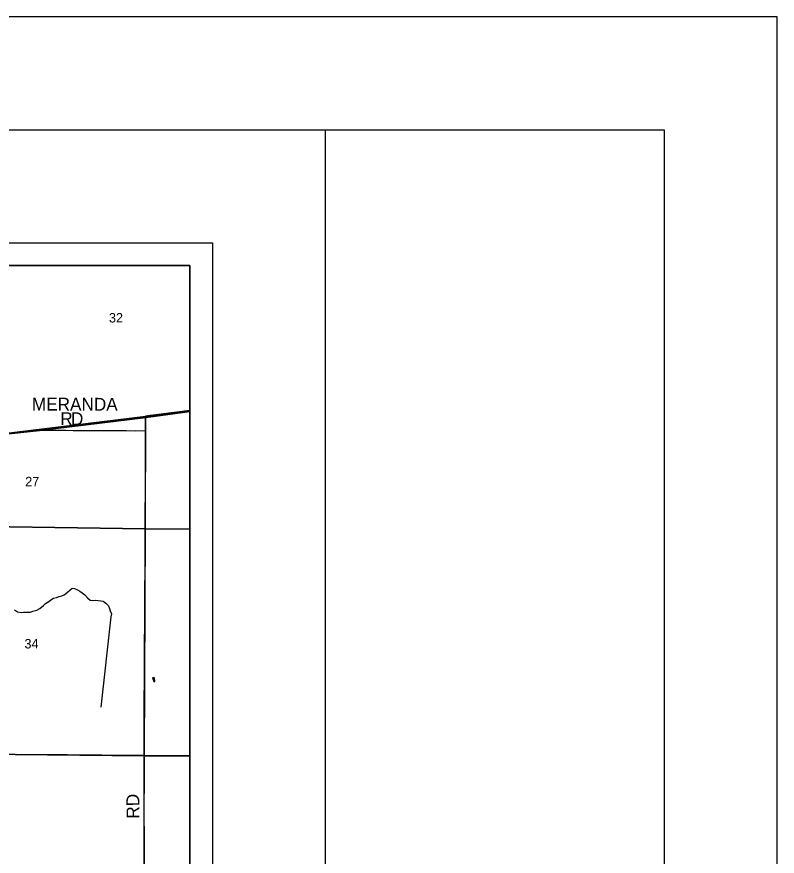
# Model space of a CAD drawing. Extents: x 0 to 1391, y -24 to 440.
# Drawn here: x 612.7 to 680, y 365.7 to 440 of the extents above; entities that cross this region are included whole.
import ezdxf

# ---------------------------------------------------------------- set-up
doc = ezdxf.new("R2010")
doc.units = 0
for name, color, linetype in [('GM_X_County_Road', 7, 'Continuous'), ('GM_X_County_Road_Text', 7, 'Continuous'), ('GM_X_Minor_Lake', 7, 'Continuous'), ('GM_X_Minor_River', 7, 'Continuous'), ('GM_X_Section', 7, 'Continuous'), ('GM_X_Section_Text', 7, 'Continuous'), ('GM_X_Township', 7, 'Continuous'), ('SH_Border', 7, 'Continuous'), ('SH_Cut_Line', 7, 'Continuous'), ('SH_Data', 7, 'Continuous')]:
    doc.layers.add(name, color=color, linetype=linetype)

msp = doc.modelspace()

# ---------------------------------------------------------------- linework, layer by layer
at = {"layer": 'GM_X_County_Road'}
for points in [[(624.066, 403.373), (624.064, 403.734), (624.056, 404.256), (624.058, 404.378), (624.061, 404.422), (624.064, 404.452), (624.069, 404.484), (624.077, 404.512), (624.085, 404.538), (624.099, 404.565), (624.107, 404.579), (624.116, 404.593), (624.129, 404.61), (624.147, 404.628), (624.171, 404.649), (624.196, 404.667), (624.224, 404.682), (624.255, 404.694), (624.289, 404.704), (624.327, 404.712), (624.366, 404.718), (624.473, 404.736), (625.011, 404.799), (625.098, 404.808), (625.531, 404.859), (626.147, 404.935), (626.627, 404.996), (627.219, 405.072), (627.785, 405.147), (628, 405.176)], [(604.058, 402.49), (604.456, 402.485), (604.969, 402.485), (605.655, 402.495), (606.005, 402.507), (606.316, 402.525), (606.787, 402.571), (607.536, 402.653), (608.265, 402.737), (608.882, 402.808), (609.301, 402.856), (610.005, 402.937), (610.372, 402.978), (610.819, 403.03), (611.574, 403.115), (612.094, 403.175), (613.214, 403.313), (613.856, 403.385), (614.215, 403.415), (614.474, 403.427), (614.788, 403.431), (615.226, 403.426)], [(615.226, 403.426), (616.325, 403.416), (617.005, 403.408), (617.667, 403.401), (618.164, 403.395), (618.985, 403.388), (619.42, 403.387), (620.385, 403.386), (620.873, 403.384), (621.363, 403.378), (621.731, 403.377), (622.377, 403.374), (623.197, 403.369), (624.066, 403.373)], [(624.033, 394.685), (624.034, 395.355), (624.047, 396.709), (624.05, 397.356), (624.05, 398.462), (624.052, 398.996), (624.056, 399.53), (624.059, 400.313), (624.063, 401.121), (624.065, 401.804), (624.067, 402.388), (624.066, 403.373)], [(623.942, 374.658), (623.944, 375.622), (623.942, 376.604), (623.938, 377.312), (623.948, 378.43), (623.958, 379.772), (623.964, 381.04), (623.974, 382.829), (623.978, 383.96), (623.979, 384.519), (623.989, 386.271), (623.997, 387.837), (624.005, 388.583), (624.012, 389.403), (624.02, 390.857), (624.022, 391.453), (624.027, 392.236), (624.03, 393.23), (624.029, 393.64), (624.033, 394.436), (624.033, 394.685)], [(624.033, 394.685), (624.095, 394.685), (624.369, 394.687), (625.189, 394.686), (627.091, 394.683), (628, 394.684)], [(612.641, 374.74), (613.834, 374.729), (614.977, 374.718), (615.648, 374.713), (616.294, 374.708), (617.151, 374.702), (617.971, 374.695), (618.705, 374.691), (620.208, 374.678), (621.488, 374.669), (622.246, 374.662), (622.83, 374.657), (623.427, 374.653), (623.775, 374.657), (623.942, 374.658)], [(623.916, 359.361), (623.916, 359.68), (623.919, 360.426), (623.916, 360.96), (623.914, 361.42), (623.915, 361.904), (623.922, 362.761), (623.924, 363.433), (623.933, 364.588), (623.963, 365.333), (623.974, 365.855), (623.977, 366.29), (623.969, 367.47), (623.962, 368.129), (623.958, 368.663), (623.955, 369.222), (623.947, 370.204), (623.947, 370.937), (623.942, 372.764), (623.942, 373.46), (623.941, 374.466), (623.942, 374.658)]]:
    msp.add_lwpolyline(points, dxfattribs=at)
at = {"layer": 'GM_X_Minor_Lake'}
for p, q in [((624.873, 381.486), (624.683, 381.513)), ((624.796, 381.168), (624.901, 381.169))]:
    msp.add_line(p, q, dxfattribs=at)
for points in [[(624.683, 381.513), (624.796, 381.168)], [(624.901, 381.169), (624.873, 381.486)]]:
    msp.add_lwpolyline(points, dxfattribs=at)
at = {"layer": 'GM_X_Minor_River'}
msp.add_line((621.002, 386.887), (620.104, 378.903), dxfattribs=at)
msp.add_lwpolyline([(612.473, 387.504), (612.743, 387.353), (613.061, 387.292), (613.274, 387.309), (613.662, 387.315), (613.868, 387.325), (614.098, 387.402), (614.443, 387.5), (614.705, 387.631), (615.017, 387.912), (615.212, 388.09), (615.49, 388.258), (615.692, 388.405), (615.908, 388.537), (616.184, 388.621), (616.429, 388.683), (616.667, 388.746), (616.875, 388.847), (617.147, 389.076), (617.349, 389.246), (617.575, 389.439), (617.787, 389.395), (618.05, 389.282), (618.253, 389.178), (618.462, 389.021), (618.693, 388.84), (618.93, 388.575), (619.168, 388.379), (619.449, 388.334), (619.647, 388.367), (619.875, 388.346), (620.095, 388.325), (620.322, 388.274), (620.561, 388.093), (620.791, 387.874), (620.877, 387.643), (620.947, 387.421), (621.047, 387.16), (621.002, 386.887)], dxfattribs=at)
at = {"layer": 'GM_X_Section'}
for p, q in [((628, 394.664), (628, 405.157)), ((628, 374.583), (628, 394.664)), ((628, 354.534), (628, 374.583))]:
    msp.add_line(p, q, dxfattribs=at)
for points in [[(611.624, 418), (611.475, 403.113), (624.068, 404.66), (628, 405.157)], [(628, 405.157), (628, 418), (611.624, 418)], [(628, 405.157), (624.068, 404.66), (624.04, 394.677), (628, 394.664)], [(628, 394.664), (624.04, 394.677), (623.948, 374.589), (628, 374.583)], [(628, 374.583), (623.948, 374.589), (623.85, 354.548), (628, 354.534)]]:
    msp.add_lwpolyline(points, dxfattribs=at)
for points in [[(611.475, 403.113), (624.068, 404.66), (624.04, 394.677), (604.024, 394.97), (604.081, 402.218), (606.571, 402.516)], [(624.04, 394.677), (623.948, 374.589), (603.924, 374.808), (604.024, 394.97)], [(623.948, 374.589), (623.85, 354.548), (604.127, 354.67), (603.924, 374.808)]]:
    msp.add_lwpolyline(points, close=True, dxfattribs=at)
at = {"layer": 'GM_X_Township'}
for points in [[(591.623, 418), (591.526, 412.457), (591.42, 402.56), (591.398, 400.66), (604.084, 402.185), (606.11, 402.437), (611.937, 403.101), (614.669, 403.388), (624.099, 404.552), (628, 405.073)], [(628, 405.073), (628, 418), (591.623, 418)], [(628, 342.724), (628, 405.073), (624.099, 404.552), (614.669, 403.388), (611.937, 403.101), (606.11, 402.437), (604.084, 402.185), (591.398, 400.66), (588.961, 400.394), (576.025, 398.776), (564.071, 397.264), (563.918, 383.057), (563.849, 374.981), (563.833, 373.178)]]:
    msp.add_lwpolyline(points, dxfattribs=at)
at = {"layer": 'SH_Border'}
msp.add_line((640, 10), (640, 430), dxfattribs=at)
msp.add_lwpolyline([(30, 430), (670, 430), (670, 10), (30, 10)], close=True, dxfattribs=at)
at = {"layer": 'SH_Cut_Line'}
msp.add_lwpolyline([(0, 0), (680, 0), (680, 440), (0, 440)], close=True, dxfattribs=at)
at = {"layer": 'SH_Data'}
for p, q in [((490, 420), (630, 420)), ((630, 420), (630, 280)), ((492, 418), (628, 418)), ((628, 418), (628, 282))]:
    msp.add_line(p, q, dxfattribs=at)

# ---------------------------------------------------------------- texts
at = {"layer": 'GM_X_County_Road_Text'}
for s, height, rotation, p in [('MERANDA', 1.1364, 359.86462, (614.001, 405.156)), ('R', 1.136, 358.98519, (616.507, 403.877)), ('D', 1.136, 359.95689, (617.461, 403.861)), ('RD', 1.1364, 90.49197, (623.522, 369.043))]:
    msp.add_text(s, height=height, rotation=rotation, dxfattribs=at).set_placement(p)
at = {"layer": 'GM_X_Section_Text'}
for s, p in [('32', (620.827, 412.948)), ('27', (613.41, 398.448)), ('34', (613.344, 384.098))]:
    msp.add_text(s, height=0.8371, rotation=0.00001, dxfattribs=at).set_placement(p)

doc.saveas('drawing.dxf')
